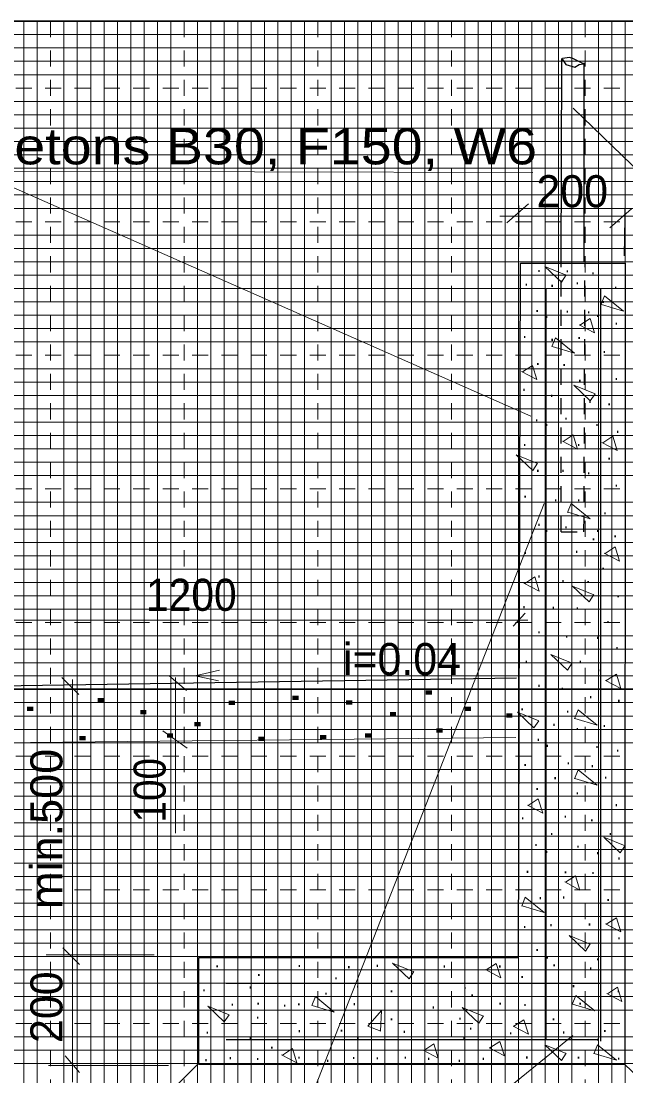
# Model space of a CAD drawing. Extents: x -265.4 to -236, y -5.8 to 40.6.
# Drawn here: x -245.09 to -240.57, y 32.7 to 40.6 of the extents above; entities that cross this region are included whole.
import ezdxf
from ezdxf.enums import TextEntityAlignment as Align

# ---------------------------------------------------------------- set-up
doc = ezdxf.new("R2010")
doc.units = 0
doc.header["$LTSCALE"] = 0.04
doc.linetypes.add('MEDIUM_DASHED', pattern=[4.5, 3, -1.5])
for name, color, linetype, lineweight in [('1', 7, 'Continuous', 13), ('2', 7, 'MEDIUM_DASHED', 13), ('3', 7, 'Continuous', 13), ('4', 7, 'Continuous', 35), ('63', 7, 'Continuous', 13)]:
    doc.layers.add(name, color=color, linetype=linetype, lineweight=lineweight)

msp = doc.modelspace()

# ---------------------------------------------------------------- linework, layer by layer
at = {"layer": '1'}
for p, q in [((-245.071, 40.598), (-245.071, 19.652)), ((-244.971, 40.598), (-244.971, 19.652)), ((-244.771, 40.598), (-244.771, 19.652)), ((-244.671, 40.598), (-244.671, 19.652)), ((-244.571, 40.598), (-244.571, 19.652)), ((-244.471, 40.598), (-244.471, 19.652)), ((-244.271, 40.598), (-244.271, 19.652)), ((-244.171, 40.598), (-244.171, 19.652)), ((-244.071, 40.598), (-244.071, 19.652)), ((-243.971, 40.598), (-243.971, 19.652)), ((-243.771, 40.598), (-243.771, 19.652)), ((-243.671, 40.598), (-243.671, 19.652)), ((-243.571, 40.598), (-243.571, 19.652)), ((-243.471, 40.598), (-243.471, 19.652)), ((-243.271, 40.598), (-243.271, 19.652)), ((-243.171, 40.598), (-243.171, 19.652)), ((-243.071, 40.598), (-243.071, 19.652)), ((-242.971, 40.598), (-242.971, 19.652)), ((-242.771, 40.598), (-242.771, 19.652)), ((-242.671, 40.598), (-242.671, 19.652)), ((-242.571, 40.598), (-242.571, 19.652)), ((-242.471, 40.598), (-242.471, 19.652)), ((-242.271, 40.598), (-242.271, 19.652)), ((-242.171, 40.598), (-242.171, 19.652)), ((-242.071, 40.598), (-242.071, 19.652)), ((-241.971, 40.598), (-241.971, 19.652)), ((-241.771, 40.598), (-241.771, 19.652)), ((-241.671, 40.598), (-241.671, 19.652)), ((-241.571, 40.598), (-241.571, 19.652)), ((-241.471, 40.598), (-241.471, 19.652)), ((-241.271, 40.598), (-241.271, 19.652)), ((-241.171, 40.598), (-241.171, 19.652)), ((-241.071, 40.598), (-241.071, 19.652)), ((-240.971, 40.598), (-240.971, 19.652)), ((-240.771, 40.598), (-240.771, 19.652)), ((-240.671, 40.598), (-240.671, 19.652)), ((-240.571, 40.598), (-240.571, 19.652)), ((-265.372, 40.497), (-236.262, 40.497)), ((-265.372, 40.397), (-236.262, 40.397)), ((-265.372, 40.297), (-236.262, 40.297)), ((-265.372, 40.197), (-236.262, 40.197)), ((-265.372, 39.997), (-236.262, 39.997)), ((-265.372, 39.897), (-236.262, 39.897)), ((-265.372, 39.797), (-236.262, 39.797)), ((-265.372, 39.697), (-236.262, 39.697)), ((-265.372, 39.497), (-236.262, 39.497)), ((-265.372, 39.397), (-236.262, 39.397)), ((-265.372, 39.297), (-236.262, 39.297)), ((-265.362, 39.196), (-236.252, 39.196)), ((-265.372, 38.997), (-236.262, 38.997)), ((-265.372, 38.897), (-236.262, 38.897)), ((-265.372, 38.797), (-236.262, 38.797)), ((-265.372, 38.697), (-236.262, 38.697)), ((-265.372, 38.497), (-236.262, 38.497)), ((-265.372, 38.397), (-236.262, 38.397)), ((-265.372, 38.297), (-236.262, 38.297)), ((-265.372, 38.197), (-236.262, 38.197)), ((-265.372, 37.997), (-236.262, 37.997)), ((-265.372, 37.897), (-236.262, 37.897)), ((-265.372, 37.797), (-236.262, 37.797)), ((-265.372, 37.697), (-236.262, 37.697)), ((-265.372, 37.497), (-236.262, 37.497)), ((-265.372, 37.397), (-236.262, 37.397)), ((-265.372, 37.297), (-236.262, 37.297)), ((-265.372, 37.197), (-236.262, 37.197)), ((-265.372, 36.997), (-236.262, 36.997)), ((-265.372, 36.897), (-236.262, 36.897)), ((-265.372, 36.797), (-236.262, 36.797)), ((-265.372, 36.697), (-236.262, 36.697)), ((-265.372, 36.497), (-236.262, 36.497)), ((-265.372, 36.397), (-236.262, 36.397)), ((-265.372, 36.297), (-236.262, 36.297)), ((-265.372, 36.197), (-236.262, 36.197)), ((-265.372, 35.997), (-236.262, 35.997)), ((-265.372, 35.897), (-236.262, 35.897)), ((-265.372, 35.797), (-236.262, 35.797)), ((-265.372, 35.698), (-236.262, 35.698)), ((-265.372, 35.498), (-236.262, 35.498)), ((-265.372, 35.398), (-236.262, 35.398)), ((-265.372, 35.298), (-236.262, 35.298)), ((-265.372, 35.198), (-236.262, 35.198)), ((-265.372, 34.998), (-236.262, 34.998)), ((-265.372, 34.898), (-236.262, 34.898)), ((-265.372, 34.798), (-236.262, 34.798)), ((-265.372, 34.698), (-236.262, 34.698)), ((-265.372, 34.498), (-236.262, 34.498)), ((-265.372, 34.398), (-236.262, 34.398)), ((-265.372, 34.298), (-236.262, 34.298)), ((-265.372, 34.198), (-236.262, 34.198)), ((-265.372, 33.998), (-236.262, 33.998)), ((-265.372, 33.898), (-236.262, 33.898)), ((-265.372, 33.798), (-236.262, 33.798)), ((-265.372, 33.698), (-236.262, 33.698)), ((-265.372, 33.498), (-236.262, 33.498)), ((-265.372, 33.398), (-236.262, 33.398)), ((-265.372, 33.298), (-236.262, 33.298)), ((-265.372, 33.198), (-236.262, 33.198)), ((-265.372, 32.998), (-236.262, 32.998)), ((-265.372, 32.898), (-236.262, 32.898)), ((-265.372, 32.798), (-236.262, 32.798))]:
    msp.add_line(p, q, dxfattribs=at)
at = {"layer": '2'}
for p, q in [((-244.871, 40.598), (-244.871, 19.652)), ((-243.871, 40.598), (-243.871, 19.652)), ((-242.871, 40.598), (-242.871, 19.652)), ((-241.871, 40.598), (-241.871, 19.652)), ((-240.871, 40.598), (-240.871, 19.652)), ((-265.372, 40.097), (-236.262, 40.097)), ((-265.372, 39.097), (-236.262, 39.097)), ((-265.372, 38.097), (-236.262, 38.097)), ((-265.372, 37.097), (-236.262, 37.097)), ((-265.372, 36.097), (-236.262, 36.097)), ((-265.372, 35.098), (-236.262, 35.098)), ((-265.372, 34.098), (-236.262, 34.098)), ((-265.372, 33.098), (-236.262, 33.098))]:
    msp.add_line(p, q, dxfattribs=at)
at = {"layer": '3'}
for p, q in [((-244.371, 40.598), (-244.371, 19.652)), ((-243.371, 40.598), (-243.371, 19.652)), ((-242.371, 40.598), (-242.371, 19.652)), ((-241.371, 40.598), (-241.371, 19.652)), ((-265.372, 39.597), (-236.262, 39.597)), ((-265.372, 38.597), (-236.262, 38.597)), ((-265.372, 37.597), (-236.262, 37.597)), ((-265.372, 36.597), (-236.262, 36.597)), ((-265.372, 34.598), (-236.262, 34.598)), ((-265.372, 33.598), (-236.262, 33.598))]:
    msp.add_line(p, q, dxfattribs=at)
at = {"layer": '4'}
for p, q in [((-265.372, 40.597), (-236.262, 40.597)), ((-265.372, 35.598), (-236.262, 35.598))]:
    msp.add_line(p, q, dxfattribs=at)
at = {"layer": '63', "lineweight": 25}
for p, q in [((-240.878, 38.796), (-240.878, 40.286)), ((-241.165, 38.593), (-241.165, 32.978)), ((-240.757, 38.593), (-240.757, 32.965)), ((-243.558, 33.398), (-240.757, 33.398)), ((-243.558, 32.978), (-240.783, 32.978))]:
    msp.add_line(p, q, dxfattribs=at)
at = {"layer": '63'}
for p, q in [((-241.295, 39.231), (-241.457, 39.088)), ((-240.579, 38.842), (-240.571, 39.263)), ((-241.367, 38.91), (-241.367, 39.219)), ((-240.524, 39.193), (-240.686, 39.05)), ((-241.509, 39.138), (-240.449, 39.138)), ((-241.319, 36.167), (-241.409, 36.071)), ((-247.452, 36.116), (-241.3, 36.116)), ((-244.786, 35.686), (-244.66, 35.56)), ((-243.986, 35.7), (-243.855, 35.588)), ((-243.937, 35.687), (-243.937, 34.521)), ((-242.892, 35.699), (-243.789, 35.699)), ((-244.708, 35.67), (-244.708, 32.658)), ((-244.03, 35.288), (-243.85, 35.157)), ((-241.391, 35.238), (-246.155, 35.188)), ((-244.78, 33.664), (-244.654, 33.538)), ((-244.097, 33.61), (-244.905, 33.61)), ((-243.573, 30.888), (-240.964, 33.008)), ((-244.762, 32.856), (-244.654, 32.73)), ((-243.989, 32.784), (-244.887, 32.784))]:
    msp.add_line(p, q, dxfattribs=at)
at = {"layer": '63', "linetype": 'MEDIUM_DASHED', "lineweight": 25}
msp.add_line((-241.05, 36.777), (-241.05, 38.777), dxfattribs=at)
at = {"layer": '63', "lineweight": 25}
for points in [[(-241.05, 38.777), (-241.047, 40.319), (-241.015, 40.273), (-240.949, 40.253), (-240.917, 40.273), (-240.884, 40.279), (-240.923, 40.299), (-240.963, 40.319), (-240.989, 40.325), (-241.041, 40.319)], [(-241.385, 35.68), (-247.35, 35.588), (-252.736, 31.992)]]:
    msp.add_lwpolyline(points, dxfattribs=at)
at = {"layer": '63'}
for points in [[(-240.962, 39.947), (-240.231, 39.241), (-236.548, 39.241)], [(-241.262, 39.464), (-245.429, 39.476), (-241.277, 37.641)], [(-241.013, 38.697), (-241.172, 38.762), (-241.049, 38.645), (-241.013, 38.699)], [(-240.75, 38.478), (-240.584, 38.428), (-240.726, 38.543), (-240.753, 38.476)], [(-240.91, 38.323), (-240.835, 38.372), (-240.802, 38.265), (-240.916, 38.325)], [(-241.118, 38.164), (-240.952, 38.114), (-241.094, 38.229), (-241.121, 38.162)], [(-241.341, 37.973), (-241.266, 38.022), (-241.233, 37.915), (-241.347, 37.975)], [(-240.797, 37.808), (-240.956, 37.873), (-240.833, 37.756), (-240.797, 37.81)], [(-241.036, 37.452), (-240.961, 37.501), (-240.928, 37.394), (-241.042, 37.454)], [(-240.74, 37.443), (-240.665, 37.492), (-240.632, 37.385), (-240.746, 37.445)], [(-241.228, 37.287), (-241.387, 37.352), (-241.264, 37.235), (-241.228, 37.289)], [(-241.178, 36.989), (-243.573, 30.888), (-236.923, 30.888)], [(-241.001, 36.924), (-240.835, 36.874), (-240.977, 36.989), (-241.004, 36.922)], [(-240.722, 36.615), (-240.647, 36.664), (-240.614, 36.557), (-240.728, 36.617)], [(-241.323, 36.39), (-241.248, 36.439), (-241.215, 36.332), (-241.329, 36.392)], [(-240.806, 36.305), (-240.965, 36.37), (-240.842, 36.253), (-240.806, 36.307)], [(-240.968, 35.793), (-241.127, 35.858), (-241.004, 35.741), (-240.968, 35.795)], [(-243.608, 35.742), (-243.789, 35.699), (-243.614, 35.661)], [(-240.713, 35.663), (-240.638, 35.712), (-240.605, 35.605), (-240.719, 35.665)], [(-240.948, 35.379), (-240.782, 35.329), (-240.924, 35.444), (-240.951, 35.377)], [(-241.219, 35.361), (-241.378, 35.426), (-241.255, 35.309), (-241.219, 35.363)], [(-240.948, 34.93), (-240.782, 34.88), (-240.924, 34.995), (-240.951, 34.928)], [(-241.297, 34.729), (-241.222, 34.778), (-241.189, 34.671), (-241.303, 34.731)], [(-240.573, 34.427), (-240.732, 34.492), (-240.609, 34.375), (-240.573, 34.429)], [(-241.018, 34.154), (-240.943, 34.203), (-240.91, 34.096), (-241.024, 34.156)], [(-241.343, 33.978), (-241.177, 33.928), (-241.319, 34.043), (-241.346, 33.976)], [(-240.713, 33.84), (-240.638, 33.889), (-240.605, 33.782), (-240.719, 33.842)], [(-240.833, 33.691), (-240.992, 33.756), (-240.869, 33.639), (-240.833, 33.693)], [(-242.153, 33.484), (-242.312, 33.549), (-242.189, 33.432), (-242.153, 33.486)], [(-241.611, 33.498), (-241.536, 33.547), (-241.503, 33.44), (-241.617, 33.5)], [(-240.704, 33.319), (-240.629, 33.368), (-240.596, 33.261), (-240.71, 33.321)], [(-242.914, 33.233), (-242.748, 33.183), (-242.89, 33.298), (-242.917, 33.231)], [(-240.965, 33.241), (-240.799, 33.191), (-240.941, 33.306), (-240.968, 33.239)], [(-243.536, 33.161), (-243.695, 33.226), (-243.572, 33.109), (-243.536, 33.163)], [(-242.4, 33.04), (-242.497, 33.076), (-242.394, 33.195), (-242.403, 33.04)], [(-241.632, 33.152), (-241.791, 33.217), (-241.668, 33.1), (-241.632, 33.154)], [(-241.404, 33.076), (-241.329, 33.125), (-241.296, 33.018), (-241.41, 33.078)], [(-242.078, 32.896), (-242.003, 32.945), (-241.97, 32.838), (-242.084, 32.898)], [(-241.584, 32.914), (-241.509, 32.963), (-241.476, 32.856), (-241.59, 32.916)], [(-241.013, 32.873), (-241.172, 32.938), (-241.049, 32.821), (-241.013, 32.875)], [(-240.804, 32.872), (-240.638, 32.822), (-240.78, 32.937), (-240.807, 32.87)], [(-243.137, 32.86), (-243.062, 32.909), (-243.029, 32.802), (-243.143, 32.862)], [(-240.575, 32.791), (-239.746, 32.003), (-244.568, 31.994), (-243.76, 32.803)]]:
    msp.add_lwpolyline(points, dxfattribs=at)
at = {"layer": '63', "lineweight": 25}
msp.add_lwpolyline([(-241.355, 38.787), (-240.571, 38.787), (-240.575, 32.791), (-243.762, 32.791), (-243.762, 33.59), (-241.371, 33.591)], close=True, dxfattribs=at)
at = {"layer": '63', "linetype": 'MEDIUM_DASHED', "lineweight": 25}
msp.add_lwpolyline([(-241.05, 36.777), (-240.88, 36.777), (-240.872, 38.79)], dxfattribs=at)

# ---------------------------------------------------------------- texts
at = {"layer": '63'}
for s, height, width, p in [('betons B30, F150, W6', 0.2707, 1.15, (-243.3025, 39.526)), ('.', 0.1, 0.85, (-241.2165, 38.721)), ('.', 0.1, 0.85, (-241.0055, 38.717)), ('.', 0.1, 0.85, (-240.8125, 38.703)), ('.', 0.1, 0.85, (-241.3115, 38.618)), ('.', 0.1, 0.85, (-241.1185, 38.609)), ('.', 0.1, 0.85, (-240.9295, 38.627)), ('.', 0.1, 0.85, (-240.6425, 38.596)), ('.', 0.1, 0.85, (-240.7365, 38.488)), ('.', 0.1, 0.85, (-241.2305, 38.42)), ('.', 0.1, 0.85, (-241.1595, 38.376)), ('.', 0.1, 0.85, (-241.0055, 38.416)), ('.', 0.1, 0.85, (-240.8445, 38.411)), ('.', 0.1, 0.85, (-240.7785, 38.384)), ('.', 0.1, 0.85, (-240.6375, 38.326)), ('.', 0.1, 0.85, (-241.3245, 38.227)), ('.', 0.1, 0.85, (-241.1185, 38.205)), ('.', 0.1, 0.85, (-240.9165, 38.218)), ('.', 0.1, 0.85, (-240.7275, 38.115)), ('.', 0.1, 0.85, (-241.2255, 38.025)), ('.', 0.1, 0.85, (-241.0285, 38.016)), ('.', 0.1, 0.85, (-240.9115, 37.899)), ('.', 0.1, 0.85, (-240.6375, 37.912)), ('.', 0.1, 0.85, (-241.3295, 37.831)), ('.', 0.1, 0.85, (-241.1225, 37.786)), ('.', 0.1, 0.85, (-240.8355, 37.741)), ('.', 0.1, 0.85, (-240.6915, 37.723)), ('.', 0.1, 0.85, (-241.2345, 37.602)), ('.', 0.1, 0.85, (-241.1595, 37.568)), ('.', 0.1, 0.85, (-241.0145, 37.616)), ('.', 0.1, 0.85, (-240.7825, 37.567)), ('.', 0.1, 0.85, (-240.6285, 37.517)), ('.', 0.1, 0.85, (-241.3245, 37.418)), ('.', 0.1, 0.85, (-240.9205, 37.418)), ('.', 0.1, 0.85, (-240.6915, 37.315)), ('.', 0.1, 0.85, (-241.2255, 37.225)), ('.', 0.1, 0.85, (-241.0375, 37.225)), ('.', 0.1, 0.85, (-240.8445, 37.207)), ('.', 0.1, 0.85, (-240.6375, 37.113)), ('.', 0.1, 0.85, (-241.3205, 37.032)), ('.', 0.1, 0.85, (-241.0915, 37.005)), ('.', 0.1, 0.85, (-240.9205, 37.005)), ('.', 0.1, 0.85, (-240.7235, 36.906)), ('.', 0.1, 0.85, (-241.2165, 36.821)), ('.', 0.1, 0.85, (-241.1595, 36.774)), ('.', 0.1, 0.85, (-241.0145, 36.803)), ('.', 0.1, 0.85, (-240.7785, 36.774)), ('.', 0.1, 0.85, (-240.8085, 36.713)), ('.', 0.1, 0.85, (-240.6465, 36.735)), ('.', 0.1, 0.85, (-241.3205, 36.61)), ('.', 0.1, 0.85, (-240.9345, 36.619)), ('.', 0.1, 0.85, (-240.7365, 36.493)), ('1200', 0.24, 0.95, (-243.818, 36.185)), ('.', 0.1, 0.85, (-241.2165, 36.434)), ('.', 0.1, 0.85, (-241.0375, 36.399)), ('.', 0.1, 0.85, (-240.8485, 36.394)), ('.', 0.1, 0.85, (-240.6245, 36.286)), ('.', 0.1, 0.85, (-241.3295, 36.205)), ('.', 0.1, 0.85, (-241.1095, 36.201)), ('.', 0.1, 0.85, (-240.9295, 36.196)), ('.', 0.1, 0.85, (-240.7005, 36.093)), ('.', 0.1, 0.85, (-241.2165, 36.017)), ('.', 0.1, 0.85, (-241.0105, 35.985)), ('.', 0.1, 0.85, (-241.1645, 35.975)), ('.', 0.1, 0.85, (-240.7785, 35.975)), ('.', 0.1, 0.85, (-240.6335, 35.9)), ('.', 0.1, 0.85, (-241.3115, 35.796)), ('.', 0.1, 0.85, (-240.9075, 35.797)), ('.', 0.1, 0.85, (-240.7585, 35.733)), ('.', 0.1, 0.85, (-241.2165, 35.616)), ('.', 0.1, 0.85, (-241.0415, 35.595)), ('.', 0.1, 0.85, (-240.8305, 35.531)), ('.', 0.1, 0.85, (-240.6195, 35.504)), ('.', 0.1, 0.85, (-241.3425, 35.441)), ('.', 0.1, 0.85, (-241.0015, 35.423)), ('.', 0.1, 0.85, (-241.1045, 35.324)), ('.', 0.1, 0.85, (-240.9295, 35.293)), ('.', 0.1, 0.85, (-240.7275, 35.315)), ('.', 0.1, 0.85, (-241.2215, 35.212)), ('.', 0.1, 0.85, (-241.1555, 35.167)), ('.', 0.1, 0.85, (-240.7825, 35.158)), ('.', 0.1, 0.85, (-240.6285, 35.131)), ('.', 0.1, 0.85, (-240.9965, 35.037)), ('.', 0.1, 0.85, (-241.3205, 35.024)), ('.', 0.1, 0.85, (-240.8175, 35.015)), ('.', 0.1, 0.85, (-241.0955, 34.925)), ('.', 0.1, 0.85, (-240.7185, 34.929)), ('.', 0.1, 0.85, (-241.2305, 34.844)), ('.', 0.1, 0.85, (-240.9295, 34.812)), ('.', 0.1, 0.85, (-240.6375, 34.723)), ('.', 0.1, 0.85, (-241.0195, 34.637)), ('.', 0.1, 0.85, (-241.3385, 34.624)), ('.', 0.1, 0.85, (-240.8215, 34.61)), ('.', 0.1, 0.85, (-241.1225, 34.507)), ('.', 0.1, 0.85, (-240.6825, 34.507)), ('.', 0.1, 0.85, (-241.2395, 34.426)), ('.', 0.1, 0.85, (-240.9255, 34.413)), ('.', 0.1, 0.85, (-241.1605, 34.373)), ('.', 0.1, 0.85, (-240.7785, 34.364)), ('.', 0.1, 0.85, (-240.6185, 34.324)), ('.', 0.1, 0.85, (-241.3025, 34.224)), ('.', 0.1, 0.85, (-241.0185, 34.22)), ('.', 0.1, 0.85, (-240.8125, 34.216)), ('.', 0.1, 0.85, (-241.2075, 34.027)), ('.', 0.1, 0.85, (-241.0325, 34.032)), ('.', 0.1, 0.85, (-240.6995, 34.014)), ('.', 0.1, 0.85, (-241.3245, 33.811)), ('.', 0.1, 0.85, (-241.1265, 33.825)), ('.', 0.1, 0.85, (-240.8385, 33.83)), ('.', 0.1, 0.85, (-240.6185, 33.726)), ('.', 0.1, 0.85, (-241.2305, 33.64)), ('.', 0.1, 0.85, (-241.1555, 33.583)), ('.', 0.1, 0.85, (-240.7785, 33.57)), ('.', 0.1, 0.85, (-243.6245, 33.517)), ('.', 0.1, 0.85, (-243.3125, 33.452)), ('.', 0.1, 0.85, (-243.0095, 33.52)), ('.', 0.1, 0.85, (-242.6395, 33.511)), ('.', 0.1, 0.85, (-242.4255, 33.521)), ('.', 0.1, 0.85, (-241.9255, 33.516)), ('.', 0.1, 0.85, (-241.5095, 33.516)), ('.', 0.1, 0.85, (-241.1035, 33.525)), ('.', 0.1, 0.85, (-240.8295, 33.502)), ('.', 0.1, 0.85, (-242.7355, 33.428)), ('.', 0.1, 0.85, (-241.3425, 33.438)), ('.', 0.1, 0.85, (-243.7225, 33.338)), ('.', 0.1, 0.85, (-243.3755, 33.359)), ('.', 0.1, 0.85, (-242.8095, 33.313)), ('.', 0.1, 0.85, (-242.5735, 33.365)), ('.', 0.1, 0.85, (-242.3205, 33.331)), ('.', 0.1, 0.85, (-241.7705, 33.355)), ('.', 0.1, 0.85, (-241.7165, 33.301)), ('.', 0.1, 0.85, (-240.9585, 33.369)), ('.', 0.1, 0.85, (-240.6235, 33.331)), ('.', 0.1, 0.85, (-243.5115, 33.23)), ('.', 0.1, 0.85, (-243.3175, 33.237)), ('.', 0.1, 0.85, (-243.1195, 33.223)), ('.', 0.1, 0.85, (-243.0135, 33.232)), ('.', 0.1, 0.85, (-242.5985, 33.234)), ('.', 0.1, 0.85, (-241.5075, 33.237)), ('.', 0.1, 0.85, (-241.3215, 33.228)), ('.', 0.1, 0.85, (-240.9085, 33.237)), ('.', 0.1, 0.85, (-242.0065, 33.209)), ('.', 0.1, 0.85, (-243.3215, 33.133)), ('.', 0.1, 0.85, (-242.3205, 33.12)), ('.', 0.1, 0.85, (-241.8085, 33.125)), ('.', 0.1, 0.85, (-241.1085, 33.12)), ('.', 0.1, 0.85, (-243.6985, 33.021)), ('.', 0.1, 0.85, (-243.3755, 32.982)), ('.', 0.1, 0.85, (-243.0095, 33.032)), ('.', 0.1, 0.85, (-242.6945, 33.035)), ('.', 0.1, 0.85, (-242.5725, 32.978)), ('.', 0.1, 0.85, (-242.2235, 33.027)), ('.', 0.1, 0.85, (-241.7785, 32.978)), ('.', 0.1, 0.85, (-241.7275, 33.05)), ('.', 0.1, 0.85, (-241.4285, 33.015)), ('.', 0.1, 0.85, (-241.0315, 33.022)), ('.', 0.1, 0.85, (-240.7245, 33.033)), ('.', 0.1, 0.85, (-243.2155, 32.909)), ('.', 0.1, 0.85, (-241.1645, 32.977)), ('.', 0.1, 0.85, (-240.9755, 32.973)), ('.', 0.1, 0.85, (-240.7785, 32.968)), ('.', 0.1, 0.85, (-243.5255, 32.83)), ('.', 0.1, 0.85, (-243.3215, 32.824)), ('.', 0.1, 0.85, (-243.0115, 32.833)), ('.', 0.1, 0.85, (-242.6035, 32.832)), ('.', 0.1, 0.85, (-242.4255, 32.828)), ('.', 0.1, 0.85, (-242.2175, 32.833)), ('.', 0.1, 0.85, (-242.0425, 32.825)), ('.', 0.1, 0.85, (-241.6335, 32.825)), ('.', 0.1, 0.85, (-241.3075, 32.835)), ('.', 0.1, 0.85, (-240.9215, 32.833)), ('.', 0.1, 0.85, (-240.6205, 32.826)), ('.', 0.1, 0.85, (-243.7075, 32.815)), ('.', 0.1, 0.85, (-242.7985, 32.81)), ('.', 0.1, 0.85, (-241.8135, 32.81))]:
    msp.add_text(s, height=height, dxfattribs=dict(at, width=width)).set_placement(p, align=Align.CENTER)
for s, p in [('200', (-240.968, 39.205)), ('i=0.04', (-242.242, 35.704))]:
    msp.add_text(s, height=0.24, dxfattribs=at).set_placement(p, align=Align.CENTER)
for s, height, width, p in [('.', 0.3, 0.85, (-244.471, 35.516)), ('.', 0.3, 0.85, (-243.015, 35.535)), ('.', 0.3, 0.85, (-242.018, 35.574)), ('.', 0.3, 0.85, (-245, 35.451)), ('.', 0.3, 0.85, (-244.154, 35.426)), ('.', 0.3, 0.85, (-243.492, 35.497)), ('.', 0.3, 0.85, (-242.614, 35.5)), ('.', 0.3, 0.85, (-241.726, 35.451)), ('.', 0.3, 0.85, (-242.286, 35.413)), ('.', 0.3, 0.85, (-241.415, 35.401)), ('.', 0.3, 0.85, (-243.748, 35.338)), ('.', 0.3, 0.85, (-241.938, 35.289)), ('.', 0.3, 0.85, (-244.608, 35.233)), ('.', 0.3, 0.85, (-243.954, 35.252)), ('.', 0.3, 0.85, (-243.27, 35.227)), ('.', 0.3, 0.85, (-242.809, 35.239)), ('.', 0.3, 0.85, (-242.473, 35.252)), ('min.500', 0.24, 1.05, (-244.782, 34.5535)), ('100', 0.24, 0.9, (-244.01, 34.8425))]:
    msp.add_text(s, height=height, rotation=90, dxfattribs=dict(at, width=width)).set_placement(p, align=Align.CENTER)
msp.add_text('200', height=0.24, rotation=90, dxfattribs=at).set_placement((-244.782, 33.219), align=Align.CENTER)

doc.saveas('drawing.dxf')
